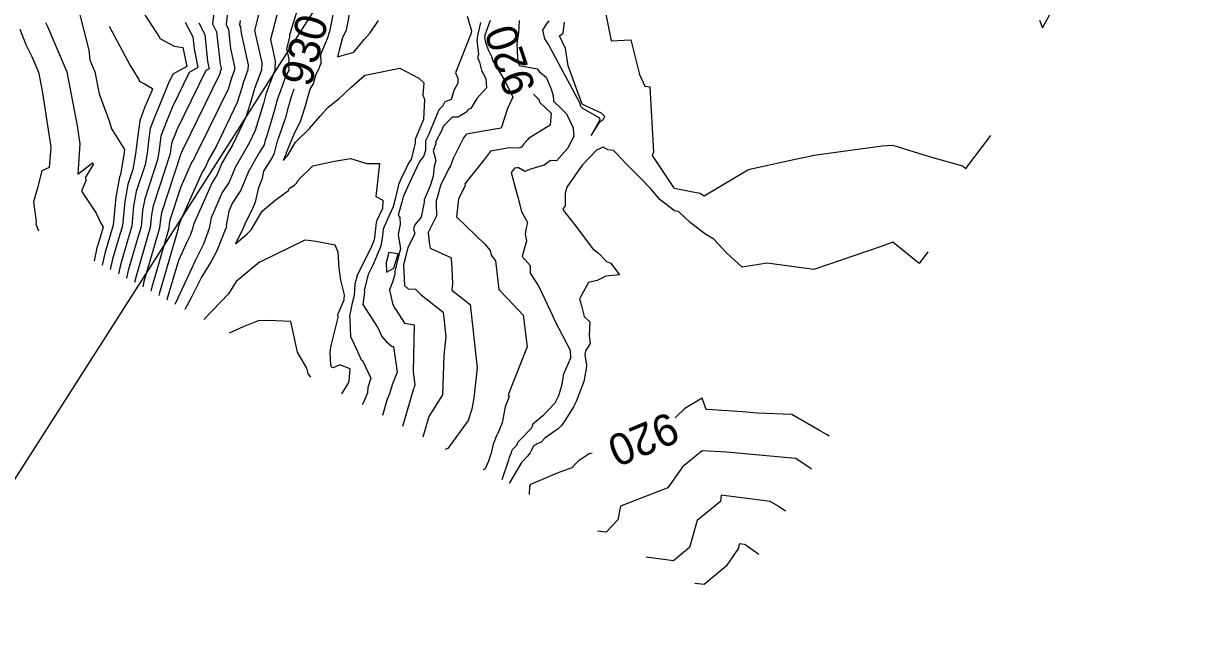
# Model space of a CAD drawing. Extents: x 1368651 to 1378602, y 762048 to 779328.
# Drawn here: x 1376956.1 to 1377329.5, y 762581 to 762773.1 of the extents above; entities that cross this region are included whole.
import ezdxf

# ---------------------------------------------------------------- set-up
doc = ezdxf.new("R2010")
doc.units = 0
for name, color, linetype in [('DTM Contours Major', 7, 'Continuous'), ('DTM Contours Major Text', 7, 'Continuous'), ('DTM Contours Minor', 7, 'Continuous'), ('Exist Plan Preparation Watershed Red', 7, 'Continuous')]:
    doc.layers.add(name, color=color, linetype=linetype)

msp = doc.modelspace()

# ---------------------------------------------------------------- linework, layer by layer
at = {"layer": 'DTM Contours Major'}
for points in [[(1377020.5, 762789.79), (1377020.38, 762789.5), (1377021.9, 762788.23), (1377022.53, 762783.11), (1377020.81, 762777.41), (1377020.23, 762772.77), (1377021.03, 762771.21), (1377021.67, 762765.13), (1377022.97, 762759.32), (1377022.92, 762758.41), (1377022.03, 762756.05), (1377021.79, 762755.12), (1377020.98, 762752.44), (1377011.76, 762733.51), (1377010.55, 762731.37), (1377010.02, 762730.1), (1377009.44, 762729.22), (1377005.89, 762721.26), (1377002.46, 762710.75), (1377002.26, 762709.63), (1377002.11, 762708.07), (1377001.81, 762707.06), (1376996.69, 762689.46), (1376996.41, 762688.23)], [(1376983.21, 762772.27), (1376989.84, 762759.74), (1376992.58, 762755.29), (1376992.88, 762754.79), (1376993.14, 762754.61), (1376994.43, 762753.99), (1376996.98, 762752.46), (1376996.7, 762751.76), (1376994.56, 762746.65), (1376992.93, 762742.18), (1376992.19, 762736.76), (1376991.58, 762731.72), (1376990.67, 762726.76), (1376989.15, 762722.09), (1376988.15, 762716.61), (1376987.44, 762708.99), (1376985.95, 762704.04), (1376984.31, 762698.42), (1376983.56, 762695.13)], [(1377041.71, 762752.27), (1377040.8, 762749.51), (1377040.13, 762747.24), (1377040.06, 762747.01), (1377039.01, 762742.9), (1377038.88, 762742.63), (1377036.86, 762736.83), (1377036.59, 762736.18), (1377035.45, 762731.95), (1377034.85, 762730.63), (1377032.12, 762726.23), (1377031.71, 762723.99), (1377030.4, 762720.72), (1377029.43, 762716.45), (1377028.71, 762714.61), (1377026.15, 762709.52), (1377025.54, 762707.94), (1377023.24, 762703.2), (1377027.05, 762706.49), (1377028.22, 762707.71), (1377031.66, 762713.59), (1377035.8, 762717.11), (1377040.03, 762720.12), (1377040.34, 762720.83), (1377041.96, 762721.83), (1377042.58, 762722.48), (1377043.12, 762723.39), (1377047.77, 762727.91), (1377054.56, 762729.47), (1377059.62, 762730.27), (1377064.78, 762728.66), (1377068.88, 762728.67), (1377067.66, 762718.27), (1377069.89, 762717.13), (1377069.75, 762714.41), (1377067.93, 762710.45), (1377067.76, 762710.05), (1377067.26, 762705.19), (1377067.08, 762704.21), (1377066.33, 762702.36), (1377061.74, 762693.17), (1377061.06, 762690.46), (1377060.78, 762686.84), (1377060.04, 762684), (1377059.35, 762680.26), (1377059.42, 762679.27), (1377059.63, 762673.72), (1377060.16, 762672.8), (1377061.96, 762668.93), (1377063.03, 762666.48), (1377063.45, 762666.25), (1377066.11, 762660.66), (1377065.2, 762657.75), (1377065.03, 762655.97), (1377063.79, 762652.93), (1377063.35, 762652.24)], [(1377117.62, 762750.71), (1377119.4, 762748.91), (1377119.52, 762748.19), (1377123.22, 762744.61), (1377122.95, 762740.8), (1377116.04, 762736.62), (1377115.6, 762736.1), (1377114.6, 762734.89), (1377113.77, 762733.84), (1377113.58, 762733.76), (1377113.13, 762733.54), (1377113.04, 762733.59), (1377110.02, 762733.63), (1377104.03, 762732.62), (1377101.79, 762729.63), (1377095.92, 762722.21), (1377096.02, 762721.86), (1377095.93, 762721.64), (1377093.9, 762717.55), (1377093.2, 762711.78), (1377102.24, 762703.12), (1377103.89, 762701.11), (1377104.19, 762699.63), (1377105.58, 762697.84), (1377106.63, 762688.8), (1377109.38, 762685.94), (1377114.3, 762680.61), (1377115.61, 762670.56), (1377109.61, 762655.35), (1377109.95, 762654.8), (1377108.63, 762651.6), (1377107.74, 762646.54), (1377106.27, 762642.96), (1377106, 762642.67), (1377104.84, 762639.71), (1377104.06, 762636.46), (1377104.02, 762636.37), (1377103.39, 762634.37), (1377102.31, 762631.87), (1377101.68, 762631.64)], [(1377211.25, 762642.23), (1377211.23, 762642.24), (1377210.37, 762642.82), (1377208.24, 762644.07), (1377199.42, 762649.19), (1377188.54, 762649.59), (1377183.81, 762650.01), (1377172.58, 762650.68), (1377172.31, 762650.74), (1377171.03, 762654.35), (1377165.56, 762651), (1377162.69, 762648.27), (1377162.59, 762648.14), (1377162.5, 762648.02)], [(1377136.16, 762636.92), (1377135.25, 762636.7), (1377131.8, 762634.36), (1377130.84, 762633.39), (1377129.72, 762632.25), (1377125.12, 762630.55), (1377116.7, 762626.96), (1377116.32, 762626.45), (1377116.26, 762623.8)]]:
    msp.add_lwpolyline(points, dxfattribs=at)
at = {"layer": 'DTM Contours Minor'}
for points in [[(1376991.32, 762780.82), (1376998.2, 762770.13), (1376999.12, 762768.68), (1376999.28, 762768.36), (1376999.48, 762768.26), (1377003.79, 762765.86), (1377006.55, 762765.45), (1377007.78, 762759.46), (1377003.37, 762757.06), (1377001.87, 762753.98), (1376999.06, 762746.89), (1376997.47, 762743.1), (1376996.26, 762739.77), (1376995.71, 762735.75), (1376995.26, 762732), (1376994.58, 762728.31), (1376991.81, 762719.82), (1376990.97, 762715.22), (1376990.38, 762708.81), (1376989.12, 762704.64), (1376986.79, 762696.62), (1376986.13, 762693.75)], [(1377016.89, 762780.8), (1377015.91, 762773.02), (1377017.25, 762770.41), (1377018.33, 762760.23), (1377018.67, 762758.7), (1377018.66, 762758.46), (1377018.42, 762757.83), (1377018.36, 762757.59), (1377018.15, 762756.88), (1377006.46, 762732.88), (1377006.35, 762732.67), (1377006.3, 762732.55), (1377006.24, 762732.47), (1377005.9, 762731.72), (1376999.8, 762713.02), (1376999.44, 762711.03), (1376999.18, 762708.26), (1376998.63, 762706.46), (1376994.22, 762691.25), (1376993.84, 762689.61)], [(1377031.9, 762781.41), (1377029.26, 762770.88), (1377031.56, 762760.56), (1377031.44, 762758.32), (1377029.23, 762752.49), (1377028.64, 762750.18), (1377026.64, 762743.55), (1377022.36, 762734.77), (1377018.95, 762728.77), (1377017.47, 762725.2), (1377015.84, 762722.72), (1377009.89, 762709.36), (1377009.65, 762707.94), (1377008.88, 762705.86), (1377007.82, 762703.77), (1377005.14, 762697.92), (1377001.64, 762685.87), (1377001.55, 762685.46)], [(1377055.02, 762780.79), (1377053, 762770.56), (1377052.28, 762768.25), (1377050.2, 762763.22), (1377050.28, 762760.45), (1377050.18, 762760.04), (1377049.87, 762759.53), (1377049.59, 762758.74), (1377048.59, 762756.66), (1377047.81, 762753.94), (1377046.87, 762752.45), (1377045.84, 762748.84), (1377045.25, 762746.83), (1377044, 762743), (1377043.81, 762742.24), (1377041.7, 762737.86), (1377041.44, 762737.13), (1377039.33, 762732.05), (1377039.25, 762731.77), (1377038.29, 762729.64), (1377039.73, 762731.14), (1377042.24, 762735.42), (1377046.69, 762739.75), (1377050, 762743.67), (1377052.51, 762746.44), (1377054.67, 762748.24), (1377056.01, 762749.17), (1377059.92, 762752.88), (1377060.28, 762753.17), (1377060.7, 762753.56), (1377060.84, 762753.78), (1377063.94, 762756.54), (1377063.96, 762756.56), (1377064.03, 762756.62), (1377064.14, 762756.64), (1377064.32, 762756.66), (1377075.25, 762758.87), (1377081.28, 762755.72), (1377082.9, 762754.24), (1377082.61, 762750.38), (1377083.06, 762749.14), (1377082.77, 762742.62), (1377080.28, 762736.63), (1377080.12, 762736.31), (1377080.15, 762735.19), (1377079.75, 762733.47), (1377078.89, 762729.94), (1377078.16, 762729.02), (1377077.39, 762727.43), (1377075.7, 762723.9), (1377074.88, 762722.03), (1377073.81, 762717.42), (1377073.14, 762714.98), (1377071.33, 762711.06), (1377070.04, 762707.87), (1377069.82, 762705.76), (1377069.24, 762702.53), (1377066.75, 762696.44), (1377065.3, 762693.53), (1377064.04, 762688.5), (1377064.07, 762687.9), (1377063.53, 762683.99), (1377068.31, 762676.66), (1377069.57, 762673.82), (1377070.91, 762672.26), (1377072.89, 762670.65), (1377073.33, 762670.66), (1377074.41, 762662.51), (1377072.89, 762658.5), (1377072.03, 762655.72), (1377071.2, 762653.73), (1377069.77, 762648.79)], [(1377277.84, 762774.11), (1377278.83, 762771.66), (1377284.27, 762781.61)], [(1376973.66, 762777.13), (1376976.76, 762764.61), (1376977.15, 762761.52), (1376978.73, 762757.8), (1376980.07, 762750.81), (1376983.3, 762741.88), (1376983.98, 762739.72), (1376984.37, 762739.06), (1376988.1, 762733.1), (1376987.9, 762731.44), (1376986.76, 762725.21), (1376986.48, 762724.36), (1376985.33, 762718.01), (1376984.51, 762709.18), (1376982.78, 762703.44), (1376981.84, 762700.21), (1376980.99, 762696.52)], [(1377042.59, 762776.54), (1377040.38, 762769.51), (1377040.36, 762768.79), (1377039.42, 762765.05), (1377040.15, 762761.8), (1377040.06, 762760.17), (1377040.16, 762758.13), (1377039.16, 762756.57), (1377038.06, 762753.21), (1377036.44, 762748.93), (1377035.49, 762745.25), (1377033.14, 762737.43), (1377032.66, 762736.08), (1377032.27, 762734.61), (1377030.87, 762732.34), (1377027.35, 762726.17), (1377024.93, 762720.3), (1377022.24, 762716.21), (1377021.09, 762713.64), (1377020.33, 762709.01), (1377020.39, 762708.67), (1377020.21, 762708.2), (1377019.94, 762707.66), (1377017.32, 762701.05), (1377015.48, 762697.6), (1377012.43, 762692.67), (1377009.16, 762686.13), (1377007.16, 762682.45)], [(1377059.25, 762775.92), (1377058.29, 762771), (1377057.1, 762768.58), (1377056.06, 762764.67), (1377055.57, 762762.53), (1377060.75, 762764.01), (1377063.99, 762768.04), (1377065.92, 762770.15), (1377068.51, 762773.98)], [(1377140.28, 762777.07), (1377142.25, 762767.61), (1377148.43, 762767.92), (1377151.16, 762756.96), (1377152.9, 762753.23), (1377154.47, 762752.95), (1377155.61, 762732.29), (1377155.22, 762731.27), (1377162, 762721.06), (1377162.14, 762720.91), (1377162.15, 762720.9), (1377162.17, 762720.89), (1377170.31, 762719.35), (1377170.52, 762719.15), (1377170.8, 762718.94), (1377171.72, 762718.42), (1377185.51, 762726.74), (1377186.53, 762726.97), (1377200.98, 762730.13), (1377206.05, 762731.28), (1377206.43, 762731.34), (1377228.06, 762734.31), (1377231.43, 762734.49), (1377242.91, 762730.95), (1377253.49, 762728.01), (1377254.56, 762727.15), (1377262.43, 762737.53)], [(1376963.03, 762773.38), (1376963.66, 762772.11), (1376969.78, 762757.74), (1376973.05, 762740.65), (1376973.93, 762734.95), (1376973.25, 762725.31), (1376977.93, 762728.87), (1376978.05, 762728.78), (1376978.17, 762728.6), (1376978.16, 762728.42), (1376975.66, 762724.17), (1376975.97, 762723.55), (1376974.46, 762719.88), (1376979.14, 762712.94), (1376980.56, 762709.83), (1376981.31, 762708.48), (1376979.6, 762702.83), (1376979.36, 762702), (1376978.42, 762697.9)], [(1377007.28, 762773.53), (1377009.7, 762768.81), (1377010.1, 762765.02), (1377011.32, 762759.09), (1377008.58, 762757.59), (1377003.26, 762746.67), (1377001.43, 762742.03), (1377000.39, 762739.55), (1376999.59, 762737.37), (1376999.23, 762734.73), (1376998.94, 762732.28), (1376998.49, 762729.87), (1376994.47, 762717.55), (1376993.79, 762713.82), (1376993.31, 762708.63), (1376992.29, 762705.25), (1376989.27, 762694.83), (1376988.7, 762692.37)], [(1377011.59, 762773.27), (1377013.47, 762769.61), (1377014.38, 762761.03), (1377014.86, 762758.71), (1377013.79, 762758.13), (1377004.66, 762739.36), (1377003.79, 762737.17), (1377003.3, 762735.99), (1377002.92, 762734.96), (1377002.75, 762733.72), (1377002.61, 762732.56), (1377002.4, 762731.42), (1376997.13, 762715.29), (1376996.62, 762712.42), (1376996.24, 762708.44), (1376995.46, 762705.85), (1376991.74, 762693.04), (1376991.27, 762690.99)], [(1377024.73, 762774.02), (1377024.54, 762772.51), (1377024.8, 762772.01), (1377025.01, 762770.03), (1377027.26, 762759.94), (1377027.18, 762758.37), (1377025.63, 762754.27), (1377025.21, 762752.65), (1377023.81, 762748), (1377017.06, 762734.14), (1377014.75, 762730.07), (1377013.75, 762727.65), (1377012.64, 762725.97), (1377005.88, 762710.81), (1377005.12, 762708.48), (1377005.08, 762708.23), (1377005.05, 762707.89), (1377004.98, 762707.66), (1376999.17, 762687.67), (1376998.98, 762686.85)], [(1377036.3, 762775.77), (1377034.34, 762767.97), (1377035.85, 762761.18), (1377035.7, 762758.28), (1377032.83, 762750.71), (1377032.06, 762747.72), (1377029.47, 762739.11), (1377027.67, 762735.39), (1377023.15, 762727.47), (1377021.2, 762722.75), (1377019.04, 762719.47), (1377015.49, 762711.5), (1377014.93, 762708.08), (1377013.07, 762703.1), (1377010.53, 762698.09), (1377004.17, 762684.17), (1377004.13, 762684.09), (1377004.12, 762684.08)], [(1377096.66, 762775.39), (1377097.94, 762770.71), (1377097.84, 762770.25), (1377097.83, 762770.19), (1377097.85, 762770.06), (1377092.93, 762757.4), (1377093.69, 762755.76), (1377093.7, 762754.15), (1377092.38, 762751.82), (1377091.73, 762749.6), (1377091.53, 762748.98), (1377089.54, 762748.23), (1377088.91, 762747.01), (1377087.63, 762745.66), (1377084.44, 762737.96), (1377083.37, 762735.9), (1377083.45, 762732.78), (1377082.76, 762730.91), (1377081.53, 762729.37), (1377079.79, 762725.79), (1377077.66, 762721.15), (1377076.33, 762718.15), (1377075.92, 762716.4), (1377074.79, 762712.28), (1377075.31, 762711.56), (1377075.41, 762709.46), (1377074.76, 762706.24), (1377075.47, 762701.65), (1377075.11, 762700.21), (1377073.66, 762694.52), (1377073.69, 762693.57), (1377072.98, 762691.12), (1377072.01, 762688.71), (1377072.96, 762684.3), (1377073.55, 762682.95), (1377074.16, 762682.24), (1377076.78, 762678.08), (1377079.81, 762677.52), (1377079.47, 762662.77), (1377080.04, 762658.44), (1377079.84, 762657.9), (1377079.72, 762657.53), (1377079.61, 762657.27), (1377076.18, 762645.35)], [(1377100.83, 762773.39), (1377100, 762769.7), (1377099.65, 762767.75), (1377100.23, 762763.2), (1377099.86, 762762.26), (1377100.53, 762760.82), (1377101.26, 762757.83), (1377101.74, 762757.04), (1377102.52, 762755.66), (1377102.74, 762752.72), (1377099.69, 762749.3), (1377097.81, 762746.1), (1377096.88, 762745.83), (1377096.54, 762745.11), (1377093.78, 762743.38), (1377092.02, 762743.42), (1377091.94, 762743.28), (1377091.74, 762743.25), (1377089.06, 762740.42), (1377088.6, 762739.29), (1377086.63, 762735.49), (1377086.64, 762734.98), (1377085.86, 762732.87), (1377086.67, 762729.62), (1377086.16, 762727.76), (1377085.85, 762724.7), (1377085.03, 762721.93), (1377084.94, 762721.62), (1377083.01, 762717.21), (1377082.98, 762716.43), (1377082.08, 762711.64), (1377080.06, 762709.3), (1377079.63, 762707.99), (1377080.08, 762706.37), (1377077.86, 762702.06), (1377077.1, 762699.05), (1377076.47, 762696.6), (1377076.72, 762690), (1377077.9, 762689.01), (1377080.25, 762688.91), (1377082.05, 762687.04), (1377089.01, 762681.56), (1377089.86, 762673.88), (1377089.2, 762667.89), (1377088.82, 762655.35), (1377084.49, 762648.53), (1377082.58, 762641.91)], [(1377103.86, 762774.03), (1377102.23, 762769.4), (1377102.17, 762769.14), (1377102.08, 762768.64), (1377102.43, 762767.08), (1377103.38, 762764.51), (1377104.37, 762762.67), (1377104.71, 762761.28), (1377108.21, 762755.44), (1377108.88, 762754.25), (1377111.08, 762749.77), (1377109.4, 762746.1), (1377107.36, 762739.93), (1377103.54, 762739.23), (1377096.43, 762738.02), (1377096.24, 762737.76), (1377095.4, 762736.83), (1377092.15, 762730.28), (1377091.31, 762727.95), (1377090.7, 762726.95), (1377090.4, 762726.13), (1377088.3, 762722.01), (1377088.11, 762721.35), (1377087, 762717.45), (1377086.8, 762716.98), (1377086.76, 762715.92), (1377086.93, 762712.14), (1377086, 762710.23), (1377084.25, 762706.83), (1377084.55, 762703.73), (1377084.88, 762701.86), (1377091.39, 762698.88), (1377091.61, 762697.38), (1377091.94, 762690.67), (1377091.78, 762688.51), (1377097.55, 762683.96), (1377099.77, 762663.96), (1377098.72, 762654.47), (1377098.07, 762650.86), (1377096.92, 762647.23), (1377090.49, 762638.41), (1377089.66, 762638.1)], [(1377113.13, 762774.04), (1377112.85, 762770.27), (1377112.33, 762766.61), (1377112.51, 762762.11), (1377113.1, 762759.76), (1377118.8, 762758.69), (1377119.54, 762757.75), (1377120.5, 762757.07), (1377121.58, 762756.03), (1377123.16, 762752.58), (1377123.81, 762750.25), (1377123.95, 762748.44), (1377126.25, 762746.22), (1377128.1, 762744.42), (1377130.15, 762739.97), (1377130.16, 762739.79), (1377130.18, 762739.65), (1377130.36, 762737.26), (1377128.56, 762733.84), (1377128.47, 762733.59), (1377124.92, 762729.58), (1377123.01, 762729.63), (1377121.01, 762728.17), (1377116.38, 762726.84), (1377114.89, 762726.12), (1377112.85, 762727.34), (1377112.44, 762727.35), (1377111.63, 762727.21), (1377111.33, 762726.81), (1377110.54, 762725.8), (1377112.65, 762718.05), (1377113.86, 762713.48), (1377115.74, 762709.97), (1377115.26, 762708.33), (1377114.99, 762706.27), (1377115.4, 762704.23), (1377114.07, 762699.27), (1377116.54, 762696.33), (1377116.6, 762693.95), (1377119.26, 762689.75), (1377123.65, 762680.5), (1377124.36, 762678.8), (1377129.25, 762669.57), (1377129.38, 762667.04), (1377127.15, 762661.9), (1377126.52, 762658.21), (1377125.52, 762655.04), (1377124.37, 762652.69), (1377120.6, 762648.72), (1377117.25, 762645.88), (1377117.31, 762645.55), (1377116.84, 762644.68), (1377115.64, 762643.46), (1377114.46, 762642.21), (1377112.68, 762640.41), (1377112.23, 762639.33), (1377110.87, 762637.9), (1377110.7, 762637.47), (1377110.59, 762637), (1377109.95, 762635.5), (1377109.69, 762634.65), (1377107.57, 762628.48)], [(1377122.47, 762773.93), (1377121.68, 762772.87), (1377120.5, 762771), (1377121.1, 762768.21), (1377122.4, 762766.33), (1377132.16, 762748.04), (1377132.4, 762747.35), (1377132.44, 762746.98), (1377132.8, 762746.61), (1377133.09, 762746.2), (1377138.52, 762743.2), (1377138.63, 762742.55), (1377135.84, 762737.62), (1377138.75, 762741.98), (1377139.68, 762742.69), (1377140.19, 762743.65), (1377139.89, 762743.89), (1377139.14, 762744.65), (1377134.32, 762746.89), (1377133, 762747.54), (1377128.6, 762759.7), (1377127.72, 762765.11), (1377125.81, 762769.15), (1377127.06, 762769.98), (1377127.4, 762773.48)], [(1376954.89, 762771.25), (1376956.83, 762766.45), (1376958.71, 762762.67), (1376960.84, 762757.67), (1376961.97, 762751.74), (1376964.73, 762733.86), (1376964.27, 762727.42), (1376961.89, 762726.34), (1376960.4, 762720.53), (1376959.21, 762716.51), (1376960.05, 762710.32), (1376960.01, 762709.47), (1376960.84, 762707.35)], [(1377242.54, 762700.68), (1377239.77, 762697.02), (1377231.46, 762703.75), (1377228.02, 762702.54), (1377206.43, 762695.13), (1377191.63, 762697.14), (1377183.71, 762695.83), (1377178.78, 762700.35), (1377174.72, 762704.77), (1377172.16, 762706.21), (1377167.3, 762709.88), (1377163.56, 762713.44), (1377162.25, 762713.69), (1377157.76, 762717.16), (1377154.63, 762720.8), (1377151.34, 762724.31), (1377147.04, 762728.47), (1377143.94, 762731.92), (1377142.96, 762732.86), (1377141.17, 762733.02), (1377139.72, 762733.87), (1377137.55, 762732.97), (1377133.07, 762728.22), (1377128.16, 762721.23), (1377127.68, 762719.3), (1377127.61, 762715.3), (1377126.93, 762714.24), (1377127.17, 762713.77), (1377130.59, 762709.41), (1377136.36, 762701.66), (1377138.15, 762700.35), (1377140.7, 762697.59), (1377142.1, 762697.09), (1377144.87, 762693.42), (1377140.5, 762692.99), (1377137.82, 762691.64), (1377135.05, 762691.01), (1377132.21, 762685.76), (1377132.7, 762683.97), (1377133.68, 762680.23), (1377135.46, 762678.47), (1377135.21, 762674.11), (1377135.59, 762671.6), (1377134.06, 762669.35), (1377133.91, 762668.08), (1377134.42, 762664.83), (1377134.25, 762663.7), (1377133.82, 762660.72), (1377133.52, 762659.57), (1377131.17, 762653.22), (1377130.32, 762651.56), (1377127.31, 762646.85), (1377126.5, 762645.67), (1377125.49, 762644.66), (1377121.22, 762641.6), (1377120.04, 762640.4), (1377118.83, 762639.86), (1377117.52, 762639.05), (1377117.06, 762638.07), (1377116.6, 762636.95), (1377115.68, 762635.93), (1377113.83, 762633.88), (1377110.03, 762627.5), (1377109.9, 762627.32), (1377109.9, 762627.22)], [(1377056.9, 762655.71), (1377058.81, 762658.73), (1377059.22, 762659.73), (1377059.59, 762663.58), (1377056.25, 762664.88), (1377054.18, 762663.97), (1377053.71, 762664.08), (1377053.48, 762664.79), (1377053.2, 762668.95), (1377053.56, 762671.06), (1377055.72, 762679.84), (1377055.68, 762680.83), (1377057.64, 762685.52), (1377057.67, 762685.65), (1377057.69, 762685.73), (1377057.79, 762687.04), (1377056.65, 762691.73), (1377056.1, 762695.68), (1377055.71, 762700.55), (1377054.84, 762702.84), (1377048.65, 762704.01), (1377046.23, 762704.32), (1377045.21, 762704.4), (1377031.16, 762697.53), (1377030.79, 762697.38), (1377023.44, 762691.3), (1377021.04, 762687.42), (1377015.92, 762682.08), (1377013.19, 762679.21)], [(1377074.74, 762700.12), (1377071.8, 762700.5), (1377070.99, 762697.32), (1377071.07, 762694.22), (1377073.34, 762695.57), (1377074.74, 762700.12)], [(1377047.11, 762660.97), (1377046.28, 762662.17), (1377045.85, 762663.78), (1377042.92, 762668.95), (1377040.78, 762678.59), (1377033.43, 762678.96), (1377030.41, 762678.81), (1377025.71, 762676.89), (1377021.18, 762674.92)], [(1377205.66, 762631.83), (1377205.56, 762631.9), (1377200.72, 762635.18), (1377200.71, 762635.19), (1377200.66, 762635.22), (1377200.6, 762635.22), (1377178.7, 762637.19), (1377170.99, 762637.65), (1377164.76, 762632.55), (1377160.15, 762625.94), (1377145.17, 762620.07), (1377144.37, 762615.78), (1377140.6, 762611.81), (1377137.94, 762612.15)], [(1377197.47, 762618.46), (1377195.41, 762619.88), (1377195.36, 762619.93), (1377192.56, 762621.59), (1377177.08, 762623.55), (1377176.84, 762621.58), (1377169.42, 762615.5), (1377167.04, 762607.03), (1377162, 762602.75), (1377153.34, 762603.87)], [(1377189.03, 762604.81), (1377184.71, 762607.79), (1377184.7, 762607.79), (1377184.4, 762607.97), (1377182.73, 762608.18), (1377182.56, 762606.74), (1377178.61, 762601.08), (1377171.7, 762595.21), (1377168.74, 762595.6)]]:
    msp.add_lwpolyline(points, dxfattribs=at)
at = {"layer": 'Exist Plan Preparation Watershed Red'}
msp.add_lwpolyline([(1373597.06, 767081.43), (1372938.47, 765818.8), (1372653.04, 765271.58), (1372900.45, 763223.22), (1372954.35, 762776.96), (1374508.77, 762195.85), (1375573.49, 762047.77), (1376441.31, 762392.26), (1376924.99, 762584.25), (1377201.49, 763017.52), (1377601.94, 763641.51), (1377736.1, 764021.28), (1377789.42, 764495.73), (1377827.52, 764834.78), (1378601.52, 765333.49), (1378471.1, 765535.9), (1378572.78, 766627.53)], dxfattribs=at)

# ---------------------------------------------------------------- texts
at = {"layer": 'DTM Contours Major Text'}
for s, rotation, p in [('930', 75.2354, (1377047.08, 762752.6)), ('920', 108.4469, (1377118.42, 762752.4)), ('920', 202.8402, (1377160.79, 762650.18))]:
    msp.add_text(s, height=10, rotation=rotation, dxfattribs=at).set_placement(p)

doc.saveas('drawing.dxf')
